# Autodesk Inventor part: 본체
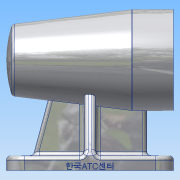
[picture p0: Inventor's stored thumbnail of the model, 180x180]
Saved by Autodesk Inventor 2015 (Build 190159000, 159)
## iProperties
Created: 2018-09
Part Number: 본체
Material: 알루미늄 6061
Document SubType Name: Modeling
Designer: user
Density: 2.7 g/cm^3
Appearance: 알루미늄 - 평지
Mass: 733.557 g
Surface Area: 666.939 cm^2
Volume: 271.688 cm^3
Author: user
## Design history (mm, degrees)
sketch "스케치2"
  geometry: L1 (56, 35)-(56, -35); L2 (56, -35)-(-56, -35); L3 (-56, -35)-(-56, 35); L4 (-56, 35)-(56, 35); L5 (56, 35)-(-56, -35); L6 (56, -35)-(-56, 35); 1 further point
  constraints: 12 end point, 2 midpoint, 2 parallel, 1 perpendicular, 1 vertical
  dimensions: "d15" = 70 distance of L1.start L1.end; "d16" = 112 distance of L1.end L2.end
extrude "돌출1" new body sketch "스케치2" distance "d17" = 10; taper "d18" = 0 deg
sketch "스케치3"
  geometry: L1 (56, 0)-(56, 74); L2 (56, 74)-(56, 108); L3 (56, 108)-(28, 108); L4 (28, 108)-(-52.27, 98.144); L5 (-56, 74)-(56, 74); L6 (56, 95)-(41, 95); L7 (41, 95)-(41, 95); L8 (38, 98)-(-10, 98); L9 (-13, 95)-(-13, 95); L10 (-25, 94.7)-(-25, 91.5); L11 (-25, 91.5)-(-42.7, 91.5); L12 (-43, 91.2)-(-43, 90); L13 (-43, 90)-(-46.7, 90); L14 (-13, 95)-(-24.7, 95); L15 (-47, 89.7)-(-47, 84.5); L16 (-47, 84.5)-(-47, 84.5); L17 (-50, 81.5)-(-50, 74); L18 (-56, 74)-(-56, 114); L19 (56, 0)-(-56, 0) reference; L20 (-56, 10)-(56, 10) reference; L21 (56, 0)-(56, 10) reference; A1 r 80 centre (24, 74) between (-52.27, 98.144) and (-56, 74); A2 r 0.3 centre (-46.7, 89.7) between (-46.7, 90) and (-47, 89.7); A3 r 0.3 centre (-42.7, 91.2) between (-42.7, 91.5) and (-43, 91.2); A4 r 0.3 centre (-24.7, 94.7) between (-24.7, 95) and (-25, 94.7); A5 r 3 centre (-10, 95) between (-10, 98) and (-13, 95); A6 r 3 centre (38, 95) between (41, 95) and (38, 98); A7 r 3 centre (-47, 81.5) between (-47, 84.5) and (-50, 81.5); 6 further points
  constraints: 36 end point, 16 point on line, 14 point on circle, 13 tangent, 8 perpendicular, 7 centre point, 5 vertical, 3 horizontal, 2 equal radius, 1 parallel
  dimensions: "d19" = 74 distance of L1.start L1.end; "d21" = 34 distance of L1.end L2.end; "d22" = 28 distance of L2.end L3.end; "d25" = 7 deg angle of L3 L4; "d26" = 80 radius of A1; "d37" = 21 distance of L1.end L6.start; "d38" = 15 distance of L6.start L6.end; "d39" = 54 distance of point (41, 98) point (-13, 98); "d41" = 12 distance of L9.end point (-25, 95); "d43" = 18 distance of L10.end point (-43, 91.5); "d44" = 24 distance between parallel lines of L5 L8; "d45" = 17.5 distance between parallel lines of L5 L11; "d48" = 3 distance of L15.end point (-50, 84.5); "d49" = 10.5 distance of point (-50, 84.5) L17.end; "d50" = 16 distance between parallel lines of L5 L13; "d51" = 4 distance of L12.end point (-47, 90); "d52" = 0.3 radius of A2; "d53" = 0.3 radius of A4; "d54" = 3 radius of A5; "d93" = 3 radius of A7; "d103" = 112 distance of L1.end L5.start; "d104" = 40 distance of L5.start L18.end
revolve "회전2" stored, may be unused: angle "d27" = 90 deg
sketch "스케치4"
  geometry: L1 (56, 10)-(-56, 10) reference; L2 (-56, 0)-(56, 0) reference; L3 (-52.27, 49.856)-(-52.27, 98.144) reference; L4 (28, 40)-(28, 108) reference; L5 (28, 40)-(28, 108) reference; L6 (56, 40)-(56, 108) reference; L7 (-52.27, 49.856)-(28, 40) reference; L8 (-38, 10)-(-20.851, 74); L9 (28, 40)-(56, 40) reference; L10 (-38, 10)-(38, 10); L11 (38, 10)-(38, 74); L12 (56, 74)-(-52.27, 74); 1 further point
  constraints: 8 end point, 4 point on line, 2 midpoint, 1 horizontal, 1 perpendicular
  dimensions: "d28" = 18 distance of L1.start L10.end; "d29" = 18 distance of L1.end L8.start; "d30" = 105 deg angle of L1 L8
extrude "돌출2" join sketch "스케치4" stored distance "d31" = 8; taper "d32" = 0 deg
sketch "스케치6"
  geometry: L1 (10, -35)-(10, 35) reference; L2 (47.177, 4)-(10, 4) reference; L3 (10, -4)-(47.177, -4) reference; L4 (47.177, 4)-(40.236, 4) reference; L5 (40.236, -4)-(47.177, -4) reference; L6 (10, 35)-(74, 11.706); L7 (10, -35)-(74, -11.706); L8 (74, 0)-(74, -24.144); L9 (74, 0)-(74, 24.144); L10 (0, -35)-(10, -35) reference; L11 (0, 35)-(10, 35) reference; L12 (10, 35)-(10, -35); L13 (74, 11.706)-(74, -11.706); A1 r 34 centre (74, 0) between (40.236, -4) and (40.236, 4) reference; A2 r 24.144 centre (74, 0) between (74, -24.144) and (74, 24.144) reference; 2 further points; 1 other entity
  constraints: 12 end point, 2 collinear, 2 point on circle, 2 point on line, 2 vertical, 1 other
  dimensions: "d33" = 20 deg angle of L10 L7; "d34" = 20 deg angle of L11 L6
extrude "돌출3" join sketch "스케치6" stored distance "d35" = 8; taper "d36" = 0 deg
revolve "회전3" stored, may be unused: angle "d55" = 90 deg
sketch "스케치7"
  geometry: C1 r 21 at (0, 0) reference; 2 further points
  constraints: 1 vertical alignment
  dimensions: "d56" = 26 distance of C1.centre point (0, 26)
hole "구멍1" sketch "스케치7" at (0, 26) diameter "d57" = 3.242; stored, may be unused: countersink angle "d61" = 90 deg, drill point angle "d63" = 118 deg; dims "d58" = 8, "d59" = 4, "d60" = 2, "d62" = 11
sketch "스케치8"
  geometry: L1 (-56, 35)-(-56, -35) reference; L2 (-56, -35)-(-4, -35) reference; 3 further points
  dimensions: "d67" = 12 distance from line of L1 point (-44, 23); "d68" = 12 horizontal distance of L1.start point (-44, 23); "d69" = 12 horizontal distance of L1.end point (-44, -23); "d70" = 12 distance from line of point (-44, -23) L2
hole "구멍2" sketch "스케치8" at (-44, 23), (-44, -23) diameter "d71" = 5.5; stored, may be unused: countersink angle "d75" = 90 deg, drill point angle "d77" = 0 deg; dims "d72" = 8, "d73" = 9.5, "d74" = 5.4, "d76" = 11
sketch "스케치9"
  geometry: L1 (112, 0)-(0, 0) reference; L2 (112, 0)-(112, 10) reference; 2 further points
  constraints: 1 other
  dimensions: "d78" = 3 distance from line of L1 point (56, 3); "d79" = 56 distance from line of L2 point (56, 3)
feature "엠보싱1" sketch "스케치9" dims "d15" = 70, "d16" = 112, "d80" = 0.5, "d81" = 0
fillet "모깎기1" dims "d82" = 12
fillet "모깎기4" dims "d85" = 3
chamfer "모따기1" distance "d86" = 1; stored, may be unused: second distance "d87" = 2, angle "d88" = 45 deg
fillet "모깎기8" dims "d92" = 3
fillet "모깎기11" dims "d96" = 3
fillet "모깎기12" dims "d97" = 3
fillet "모깎기13" dims "d98" = 3
fillet "모깎기14" dims "d99" = 3
node "솔리드2"
pattern_circular "원형 패턴1" dims angle "d65" = 360 deg
mirror "대칭1"
node "투영된 루프1"
node "투영된 루프2"
node "투영된 루프3"
